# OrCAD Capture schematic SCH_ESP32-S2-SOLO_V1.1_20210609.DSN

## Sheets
1 01_DesignBlock: title: <ESP32-S2-SOLO>; rev: V1.1; note: <01_DesignBlock>
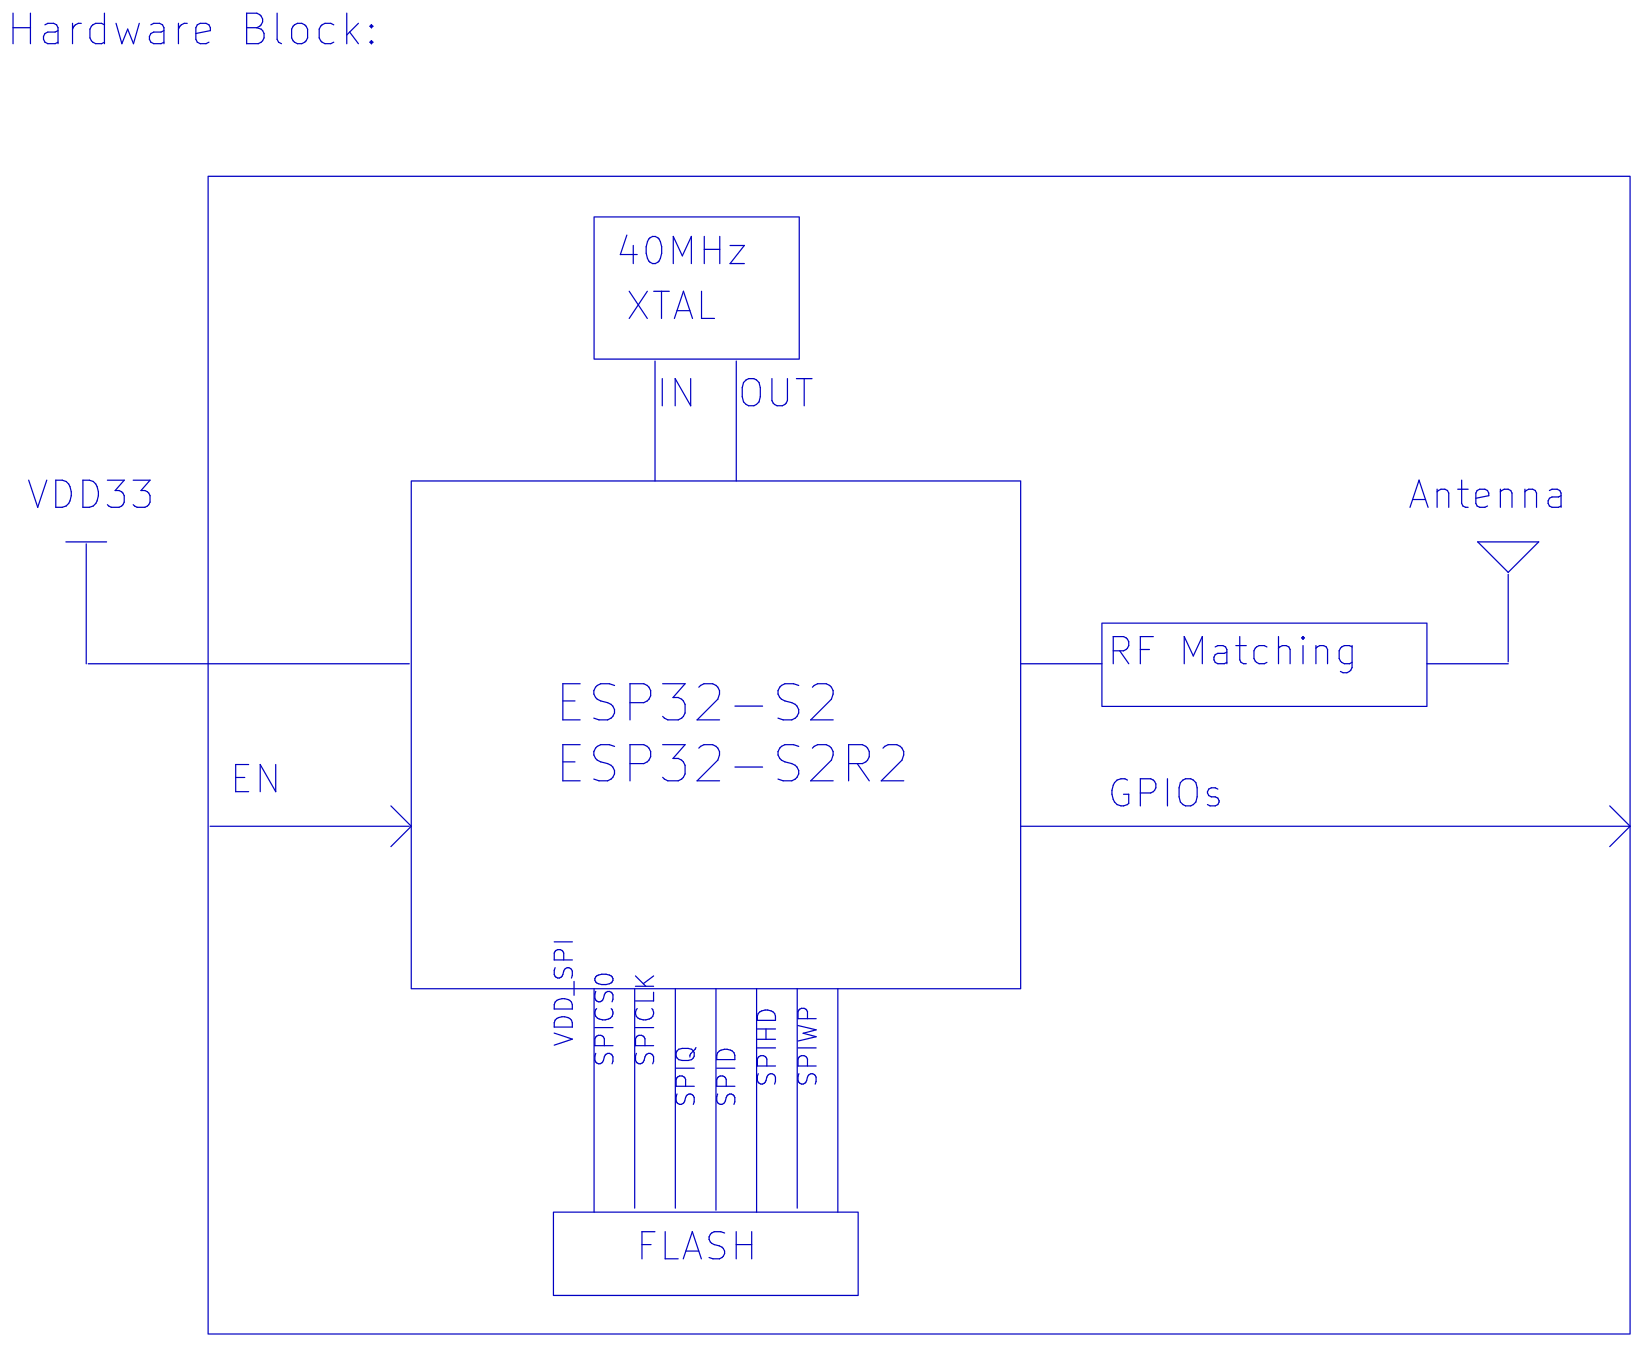
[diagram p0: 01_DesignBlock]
2 02_ESP32-S2-SOLO: size A4; note: <02_ESP32-S2-SOLO>
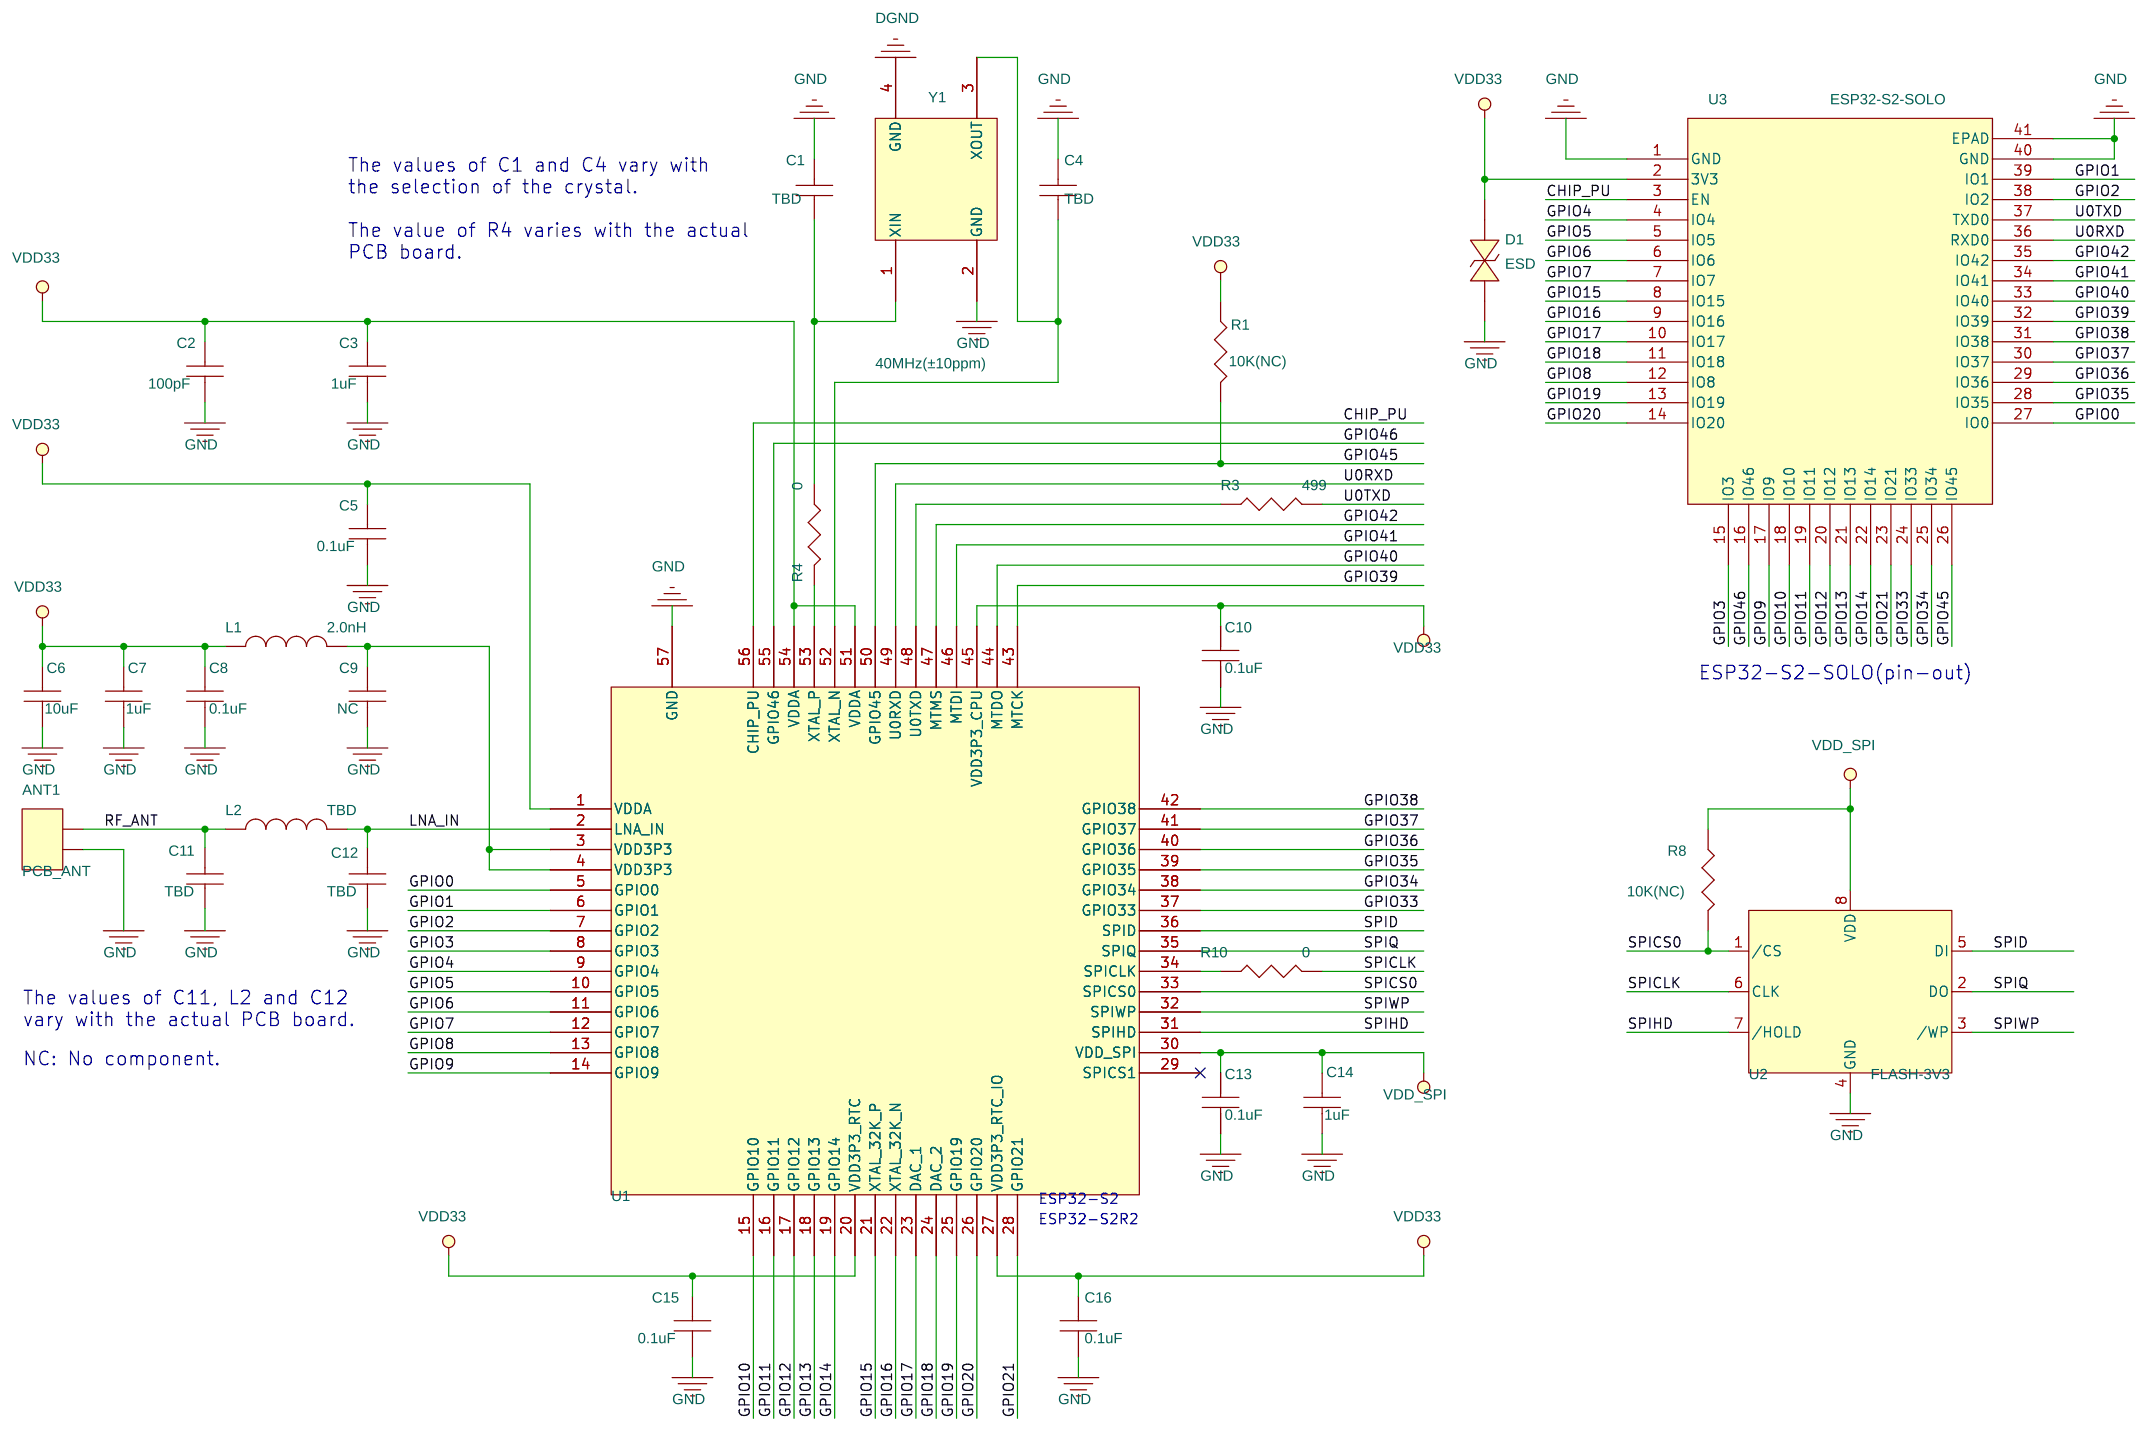
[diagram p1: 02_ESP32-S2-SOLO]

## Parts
ANT1  PCB_ANT  [MINI_ANT_TYPEB]
C1  TBD  [C0201]
C2  100pF  [C0201]
C3  1uF  [C0201]
C4  TBD  [C0201]
C5  0.1uF  [C0201]
C6  10uF  [C0402]
C7  1uF  [C0201]
C8  0.1uF  [C0201]
C9  NC  [C0201]
C10  0.1uF  [C0201]
C11  TBD  [C0201]
C12  TBD  [C0201]
C13  0.1uF  [C0201]
C14  1uF  [C0201]
C15  0.1uF  [C0201]
C16  0.1uF  [C0201]
D1  ESD  [SOD882]
L1  2.0nH  [L0201]
L2  TBD  [L0201]
R1  10K(NC)  [R0201]
R3  499  [R0201]
R4  0  [R0201]
R8  10K(NC)  [R0201]
R10  0  [R0201]
U1  ESP32-S2/ESP32-S2R2  [QFN56_0P4_7]
U2  FLASH-3V3  [SOP8_1P27_6p6]
U3  ESP32-S2-SOLO  [SMD41_1P27_18]
Y1  40MHz(±10ppm)  [XTAL3225]

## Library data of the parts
ANT1 = PCB_ANT
C1-C16 = CAP
D1 = DIODE_BI-DIR_TRIG
L1 L2 = Inductor
R1 R3 R4 R8 R10 = RESISTOR_0
U1 = ESP32K
U2 = FLASH_3V3
U3 = ESP32-S2-SOLO
Y1 = X1_1

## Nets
GND: ANT1.2 C1.2 C2.2 C3.2 C4.2 C5.2 C6.2 C7.2 C8.2 C9.2 C10.2 C11.1 C12.1 C13.2 C14.2 C15.2 C16.2 D1.2 U1.57(GND) U2.4(GND) U3.1(GND) U3.40(GND) U3.41(EPAD) Y1.2(GND) Y1.4(GND)
VDD33: C2.1 C3.1 C5.1 C6.1 C7.1 C8.1 C10.1 C15.1 C16.1 D1.1 L1.1 R1.1 U1.1(VDDA) U1.20(VDD3P3_RTC) U1.27(VDD3P3_RTC_IO) U1.45(VDD3P3_CPU) U1.51(VDDA) U1.54(VDDA) U3.2(3V3)
VDD_SPI: C13.1 C14.1 R8.2 U1.30(VDD_SPI) U2.8(VDD)
CHIP_PU: U1.56(CHIP_PU) U3.3(EN)
GPIO0: U1.5(GPIO0) U3.27(IO0)
GPIO1: U1.6(GPIO1) U3.39(IO1)
GPIO2: U1.7(GPIO2) U3.38(IO2)
GPIO3: U1.8(GPIO3) U3.15(IO3)
GPIO4: U1.9(GPIO4) U3.4(IO4)
GPIO5: U1.10(GPIO5) U3.5(IO5)
GPIO6: U1.11(GPIO6) U3.6(IO6)
GPIO7: U1.12(GPIO7) U3.7(IO7)
GPIO8: U1.13(GPIO8) U3.12(IO8)
GPIO9: U1.14(GPIO9) U3.17(IO9)
GPIO10: U1.15(GPIO10) U3.18(IO10)
GPIO11: U1.16(GPIO11) U3.19(IO11)
GPIO12: U1.17(GPIO12) U3.20(IO12)
GPIO13: U1.18(GPIO13) U3.21(IO13)
GPIO14: U1.19(GPIO14) U3.22(IO14)
GPIO15: U1.21(XTAL_32K_P) U3.8(IO15)
GPIO16: U1.22(XTAL_32K_N) U3.9(IO16)
GPIO17: U1.23(DAC_1) U3.10(IO17)
GPIO18: U1.24(DAC_2) U3.11(IO18)
GPIO19: U1.25(GPIO19) U3.13(IO19)
GPIO20: U1.26(GPIO20) U3.14(IO20)
GPIO21: U1.28(GPIO21) U3.23(IO21)
GPIO33: U1.37(GPIO33) U3.24(IO33)
GPIO34: U1.38(GPIO34) U3.25(IO34)
GPIO35: U1.39(GPIO35) U3.28(IO35)
GPIO36: U1.40(GPIO36) U3.29(IO36)
GPIO37: U1.41(GPIO37) U3.30(IO37)
GPIO38: U1.42(GPIO38) U3.31(IO38)
GPIO39: U1.43(MTCK) U3.32(IO39)
GPIO40: U1.44(MTDO) U3.33(IO40)
GPIO41: U1.46(MTDI) U3.34(IO41)
GPIO42: U1.47(MTMS) U3.35(IO42)
GPIO45: R1.2 U1.50(GPIO45) U3.26(IO45)
GPIO46: U1.55(GPIO46) U3.16(IO46)
LNA_IN: C12.2 L2.1 U1.2(LNA_IN)
RF_ANT: ANT1.1 C11.2 L2.2
SPICLK: R10.2 U2.6(CLK)
SPICS0: R8.1 U1.33(SPICS0) U2.1(/CS)
SPID: U1.36(SPID) U2.5(DI)
SPIHD: U1.31(SPIHD) U2.7(/HOLD)
SPIQ: U1.35(SPIQ) U2.2(DO)
SPIWP: U1.32(SPIWP) U2.3(/WP)
U0RXD: U1.49(U0RXD) U3.36(RXD0)
U0TXD: R3.2 U3.37(TXD0)
N16980501: R3.1 U1.48(U0TXD)
N16980759: R10.1 U1.34(SPICLK)
N16981224: C9.1 L1.2 U1.3(VDD3P3) U1.4(VDD3P3)
N16989795: C4.1 U1.52(XTAL_N) Y1.3(XOUT)
N16989829: C1.1 R4.1 Y1.1(XIN)
N16994903: R4.2 U1.53(XTAL_P)

Not connected (* = marked no-connect by the designer): U1 29(SPICS1)*

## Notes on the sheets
sheet 1
- Hardware Block:
- 40MHz
- XTAL
- IN
- OUT
- VDD33
- Antenna
- RF Matching
- ESP32-S2
- EN
- ESP32-S2R2
- GPIOs
- VDD_SPI
- SPICS0
- SPICLK
- SPIHD
- SPIWP
- SPIQ
- SPID
- FLASH
sheet 2
- The values of C1 and C4 vary with
  the selection of the crystal.
  The value of R4 varies with the actual
  PCB board.
- ESP32-S2-SOLO(pin-out)
- The values of C11, L2 and C12
  vary with the actual PCB board.
- NC: No component.
- ESP32-S2
- ESP32-S2R2
